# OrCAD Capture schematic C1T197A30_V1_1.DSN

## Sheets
1 01_Block digram: title: Telink-Semi; rev: V1.1; note: C1T197A30
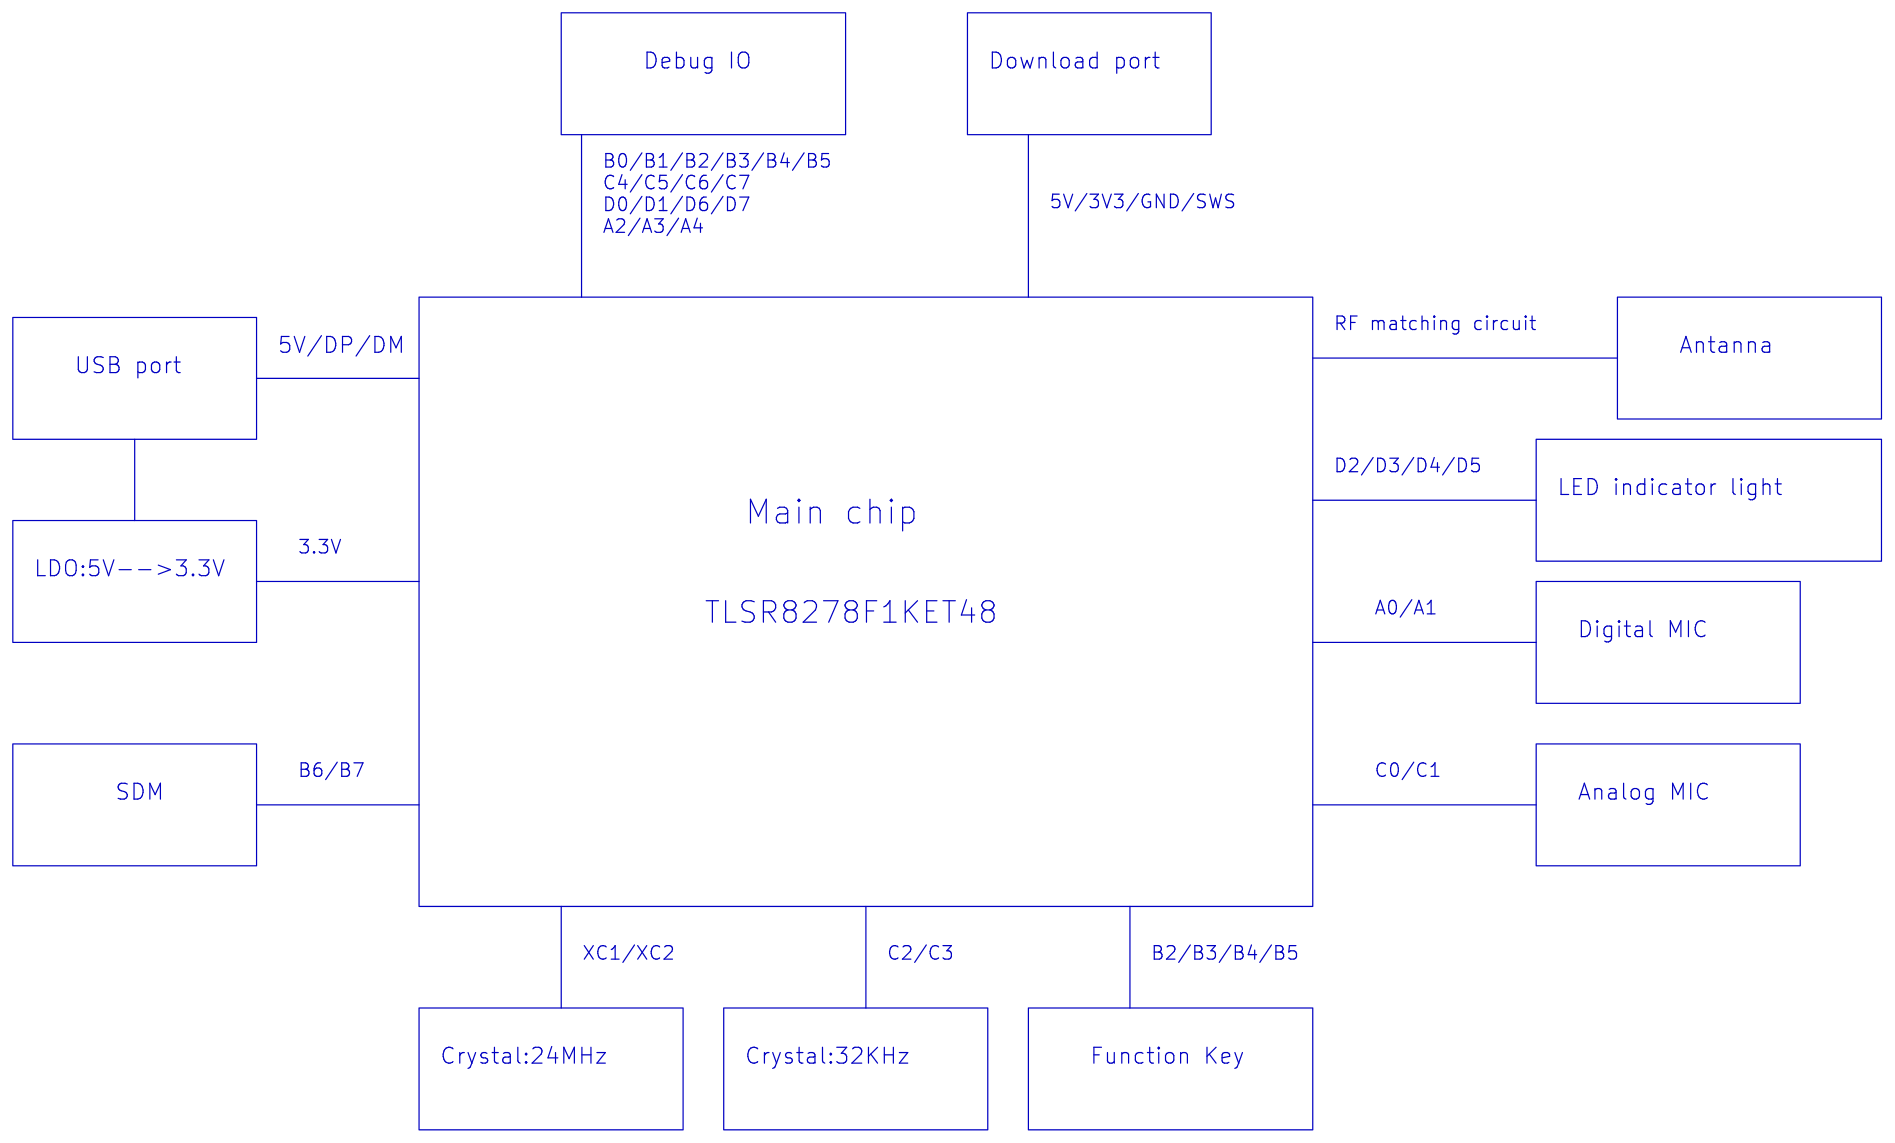
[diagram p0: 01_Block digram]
2 00_Log
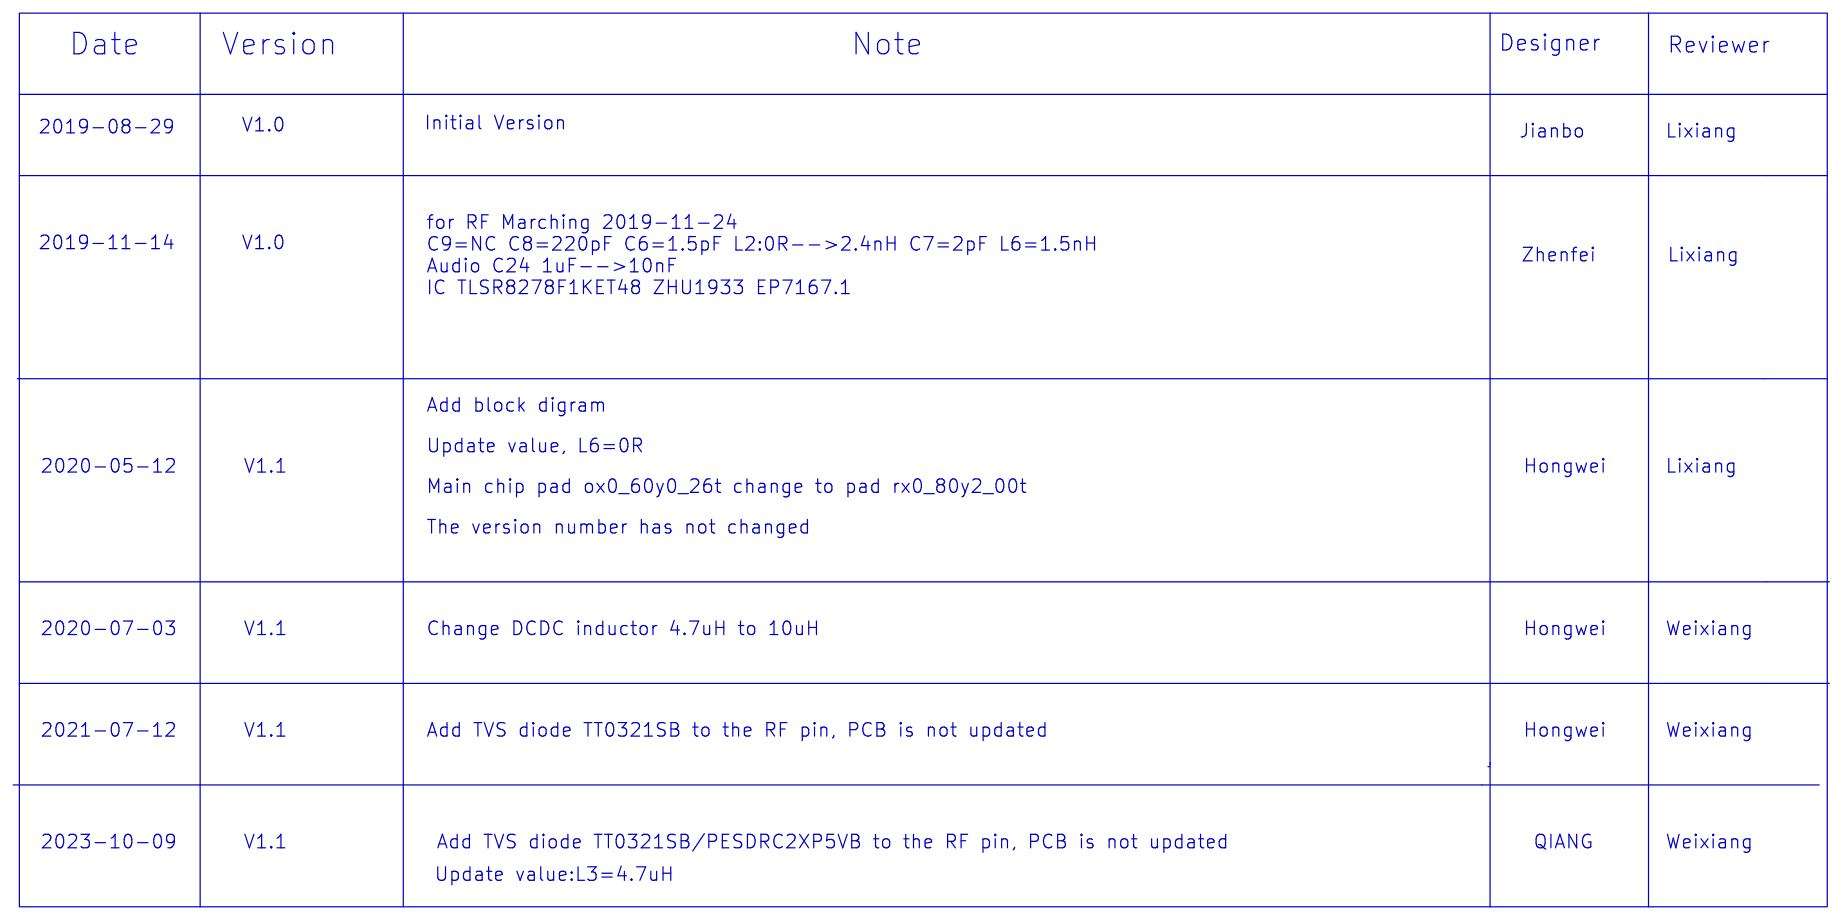
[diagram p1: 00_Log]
3 02_main: size A4
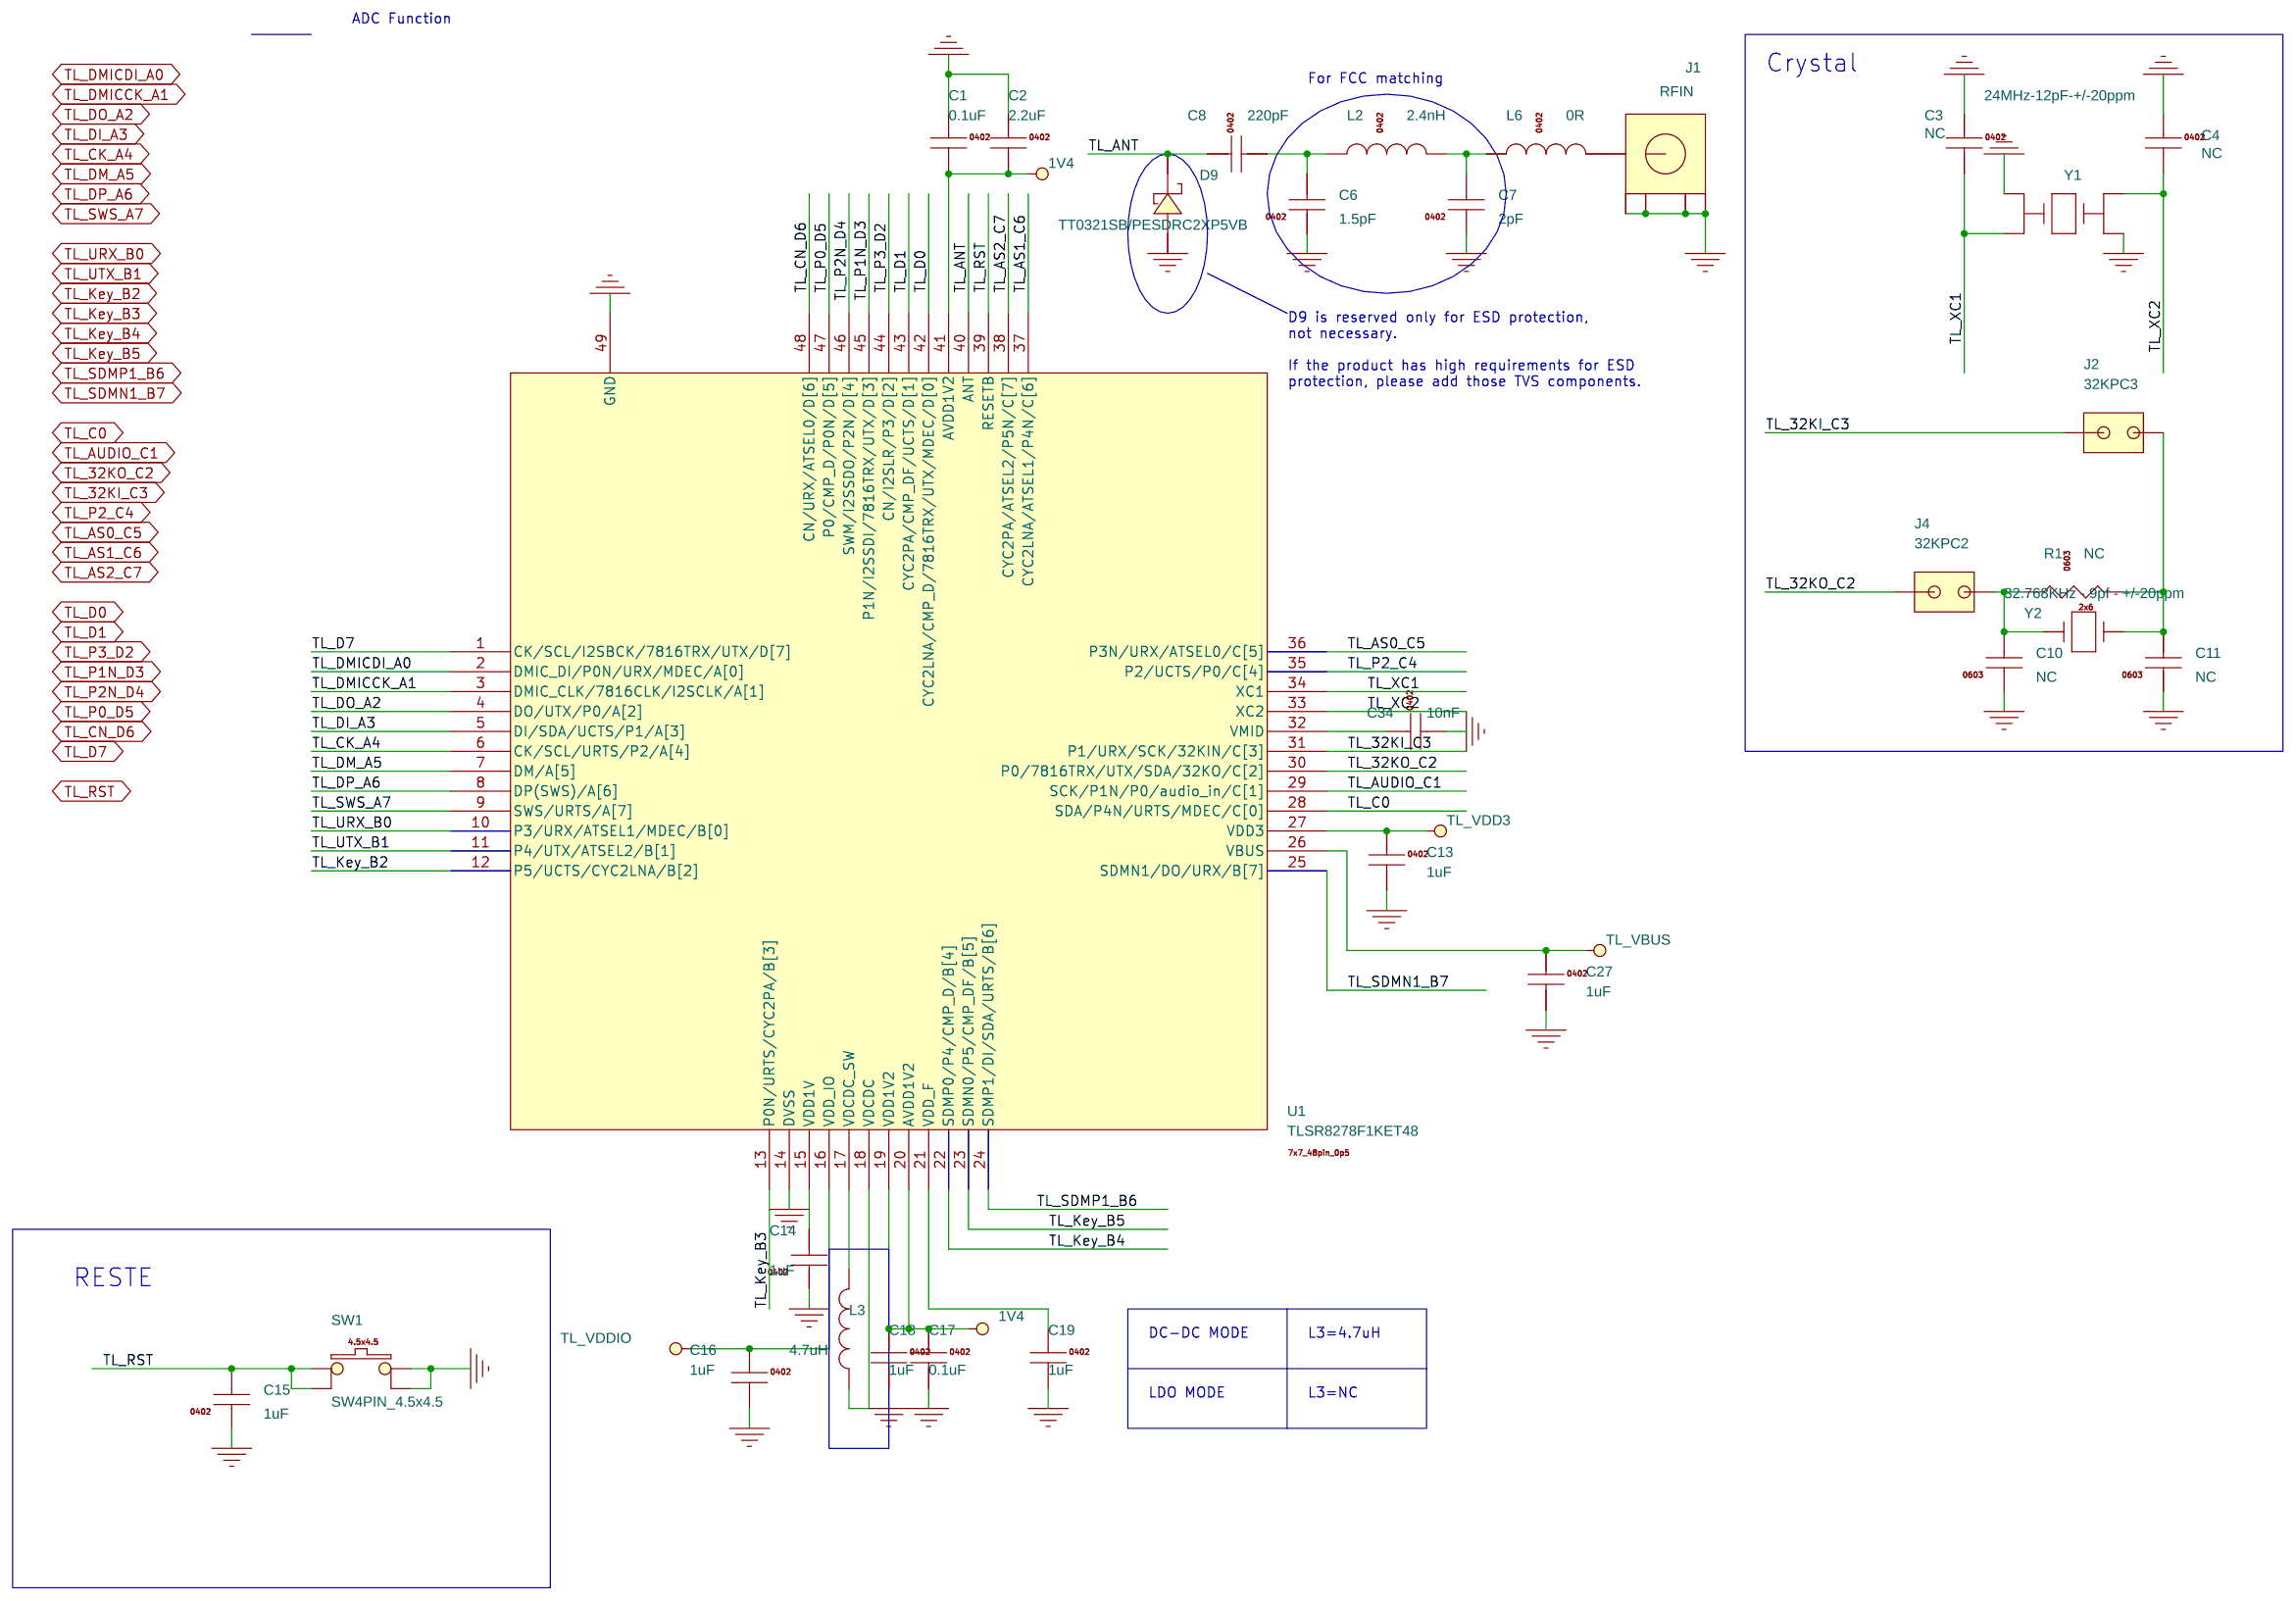
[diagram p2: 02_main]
4 03_Header: size A4
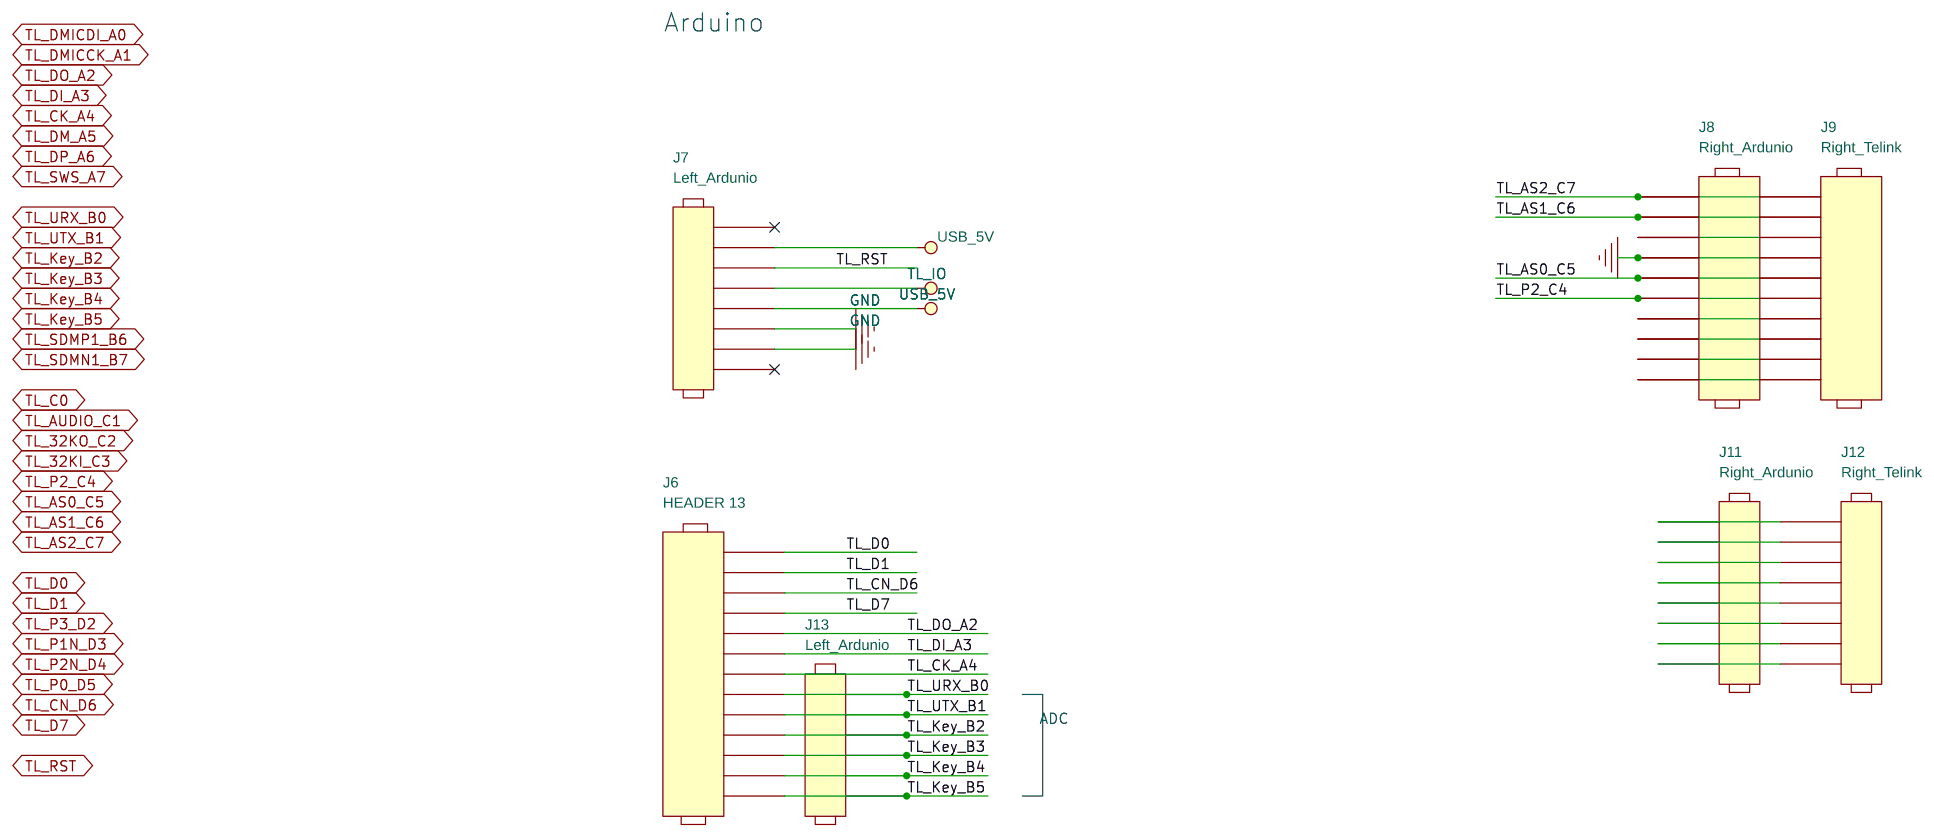
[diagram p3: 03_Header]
5 04_others: size A4
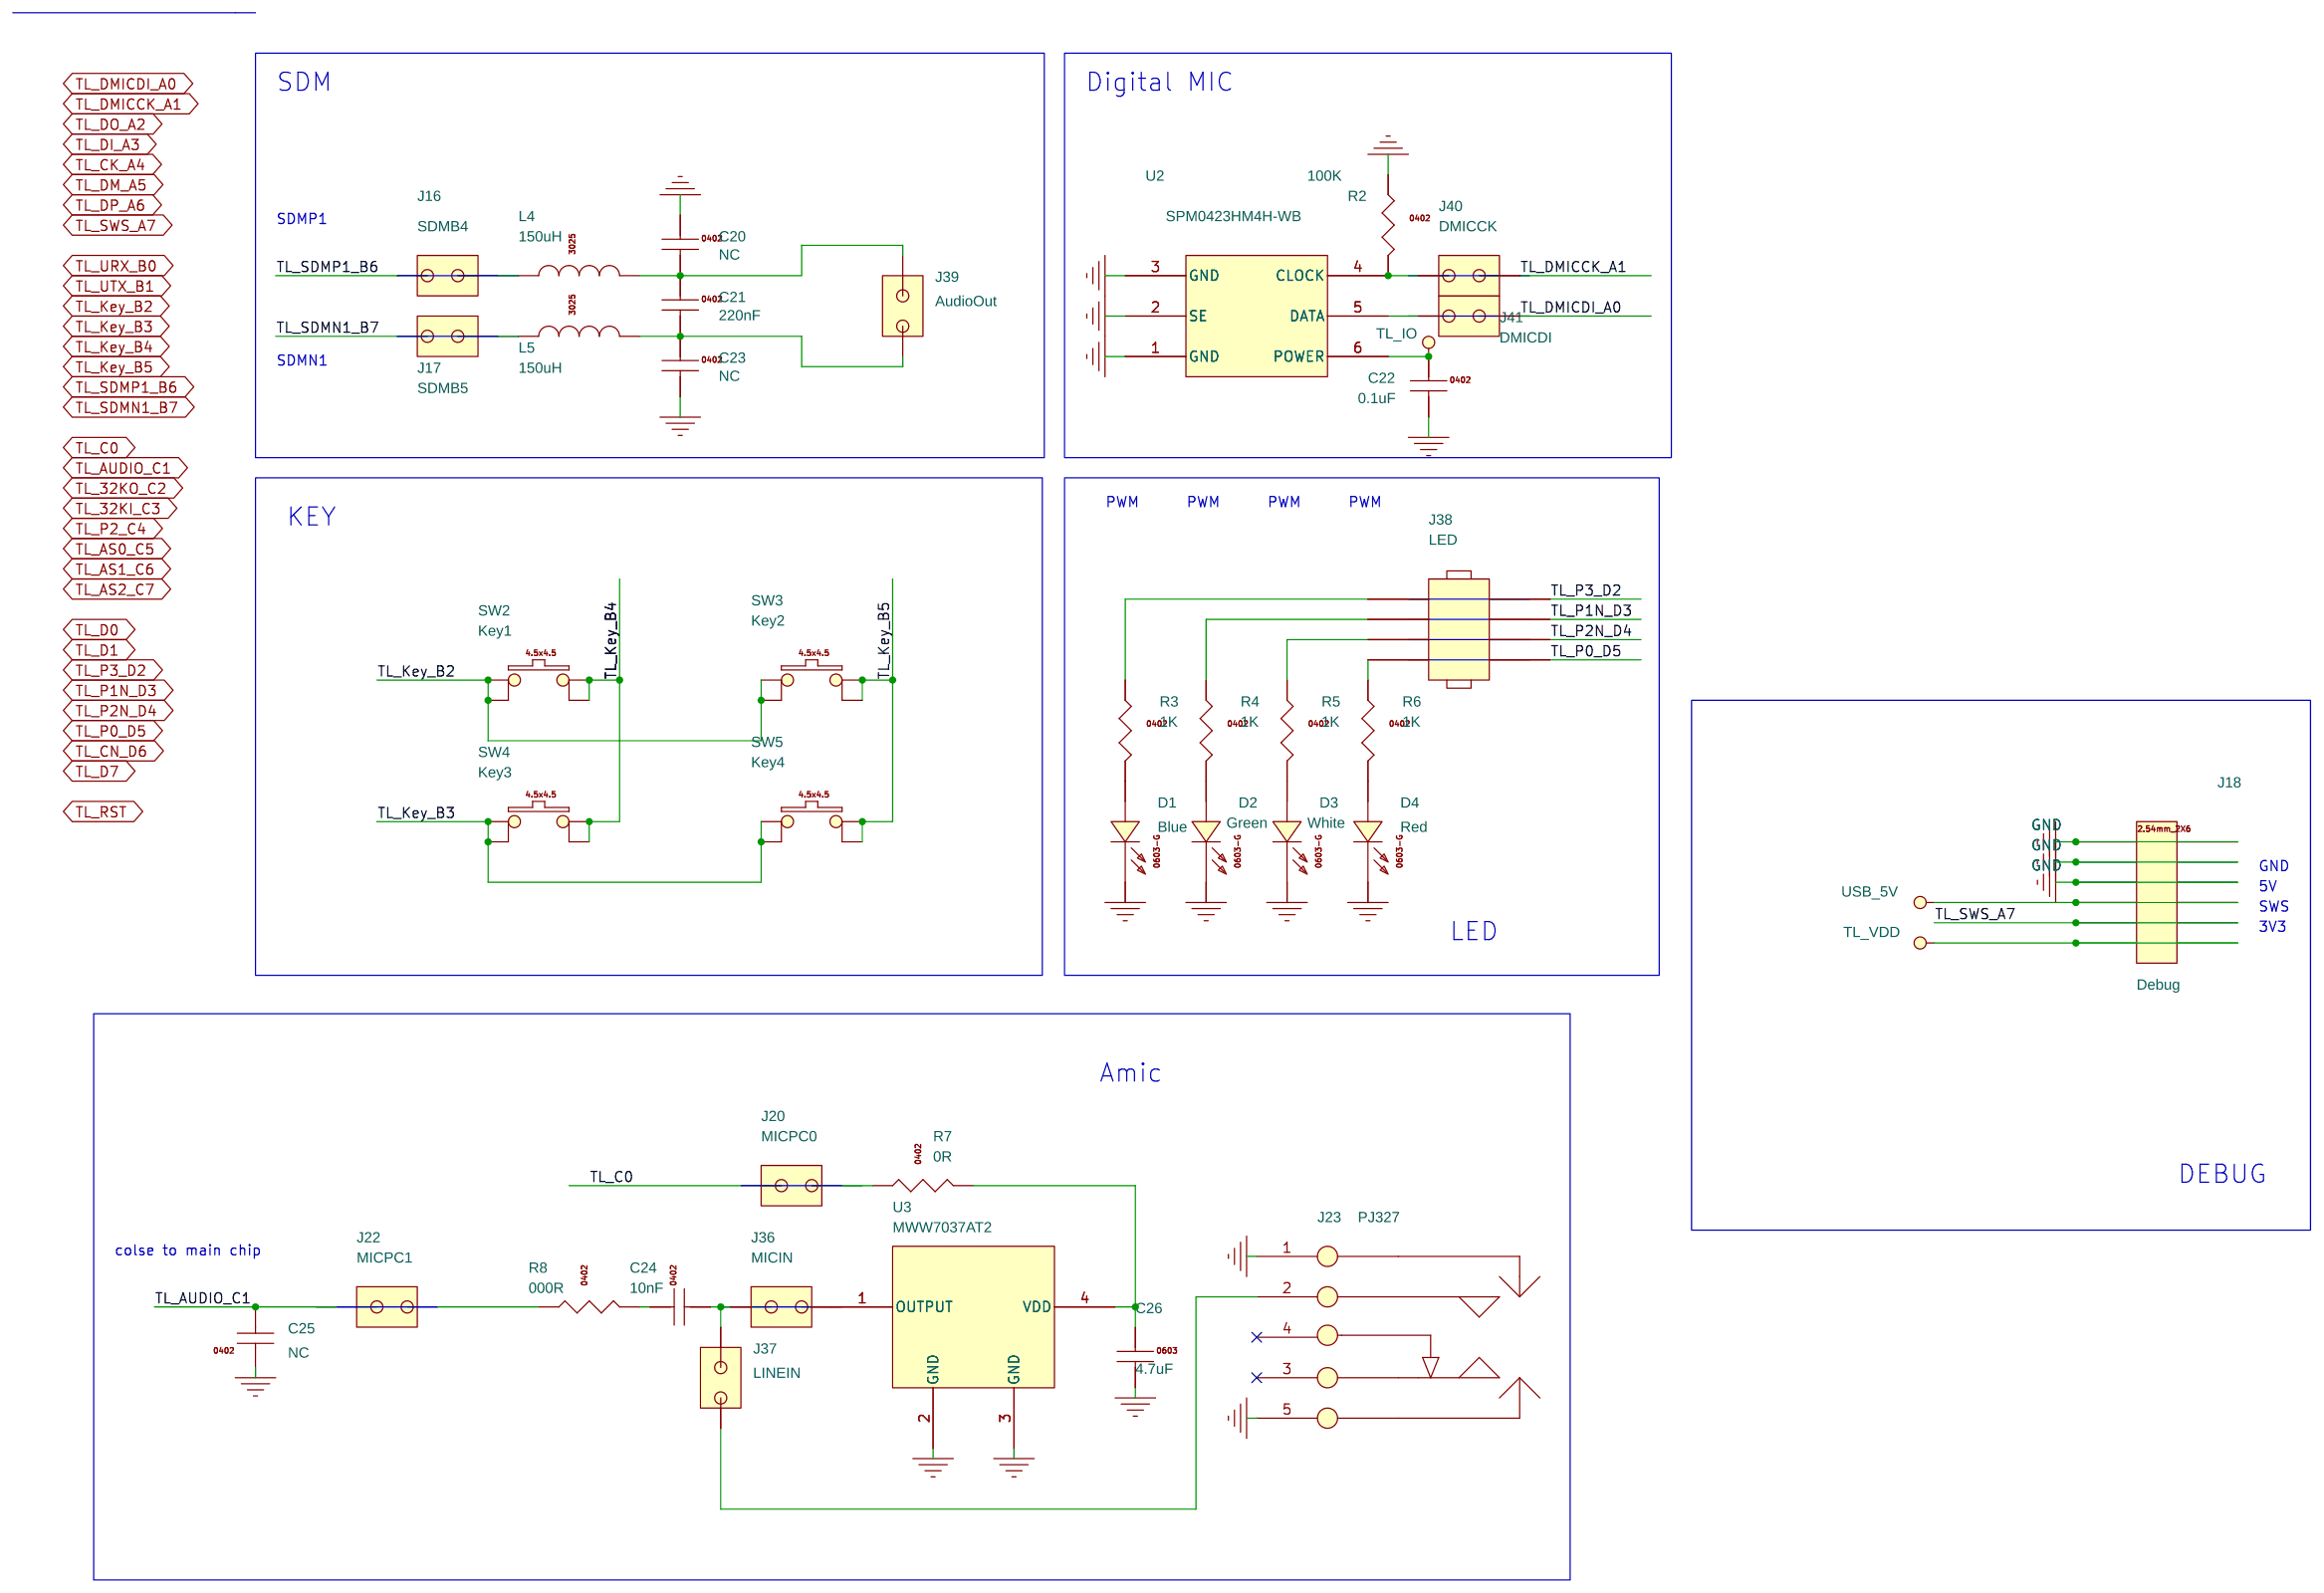
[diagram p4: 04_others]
6 05_power: size A4
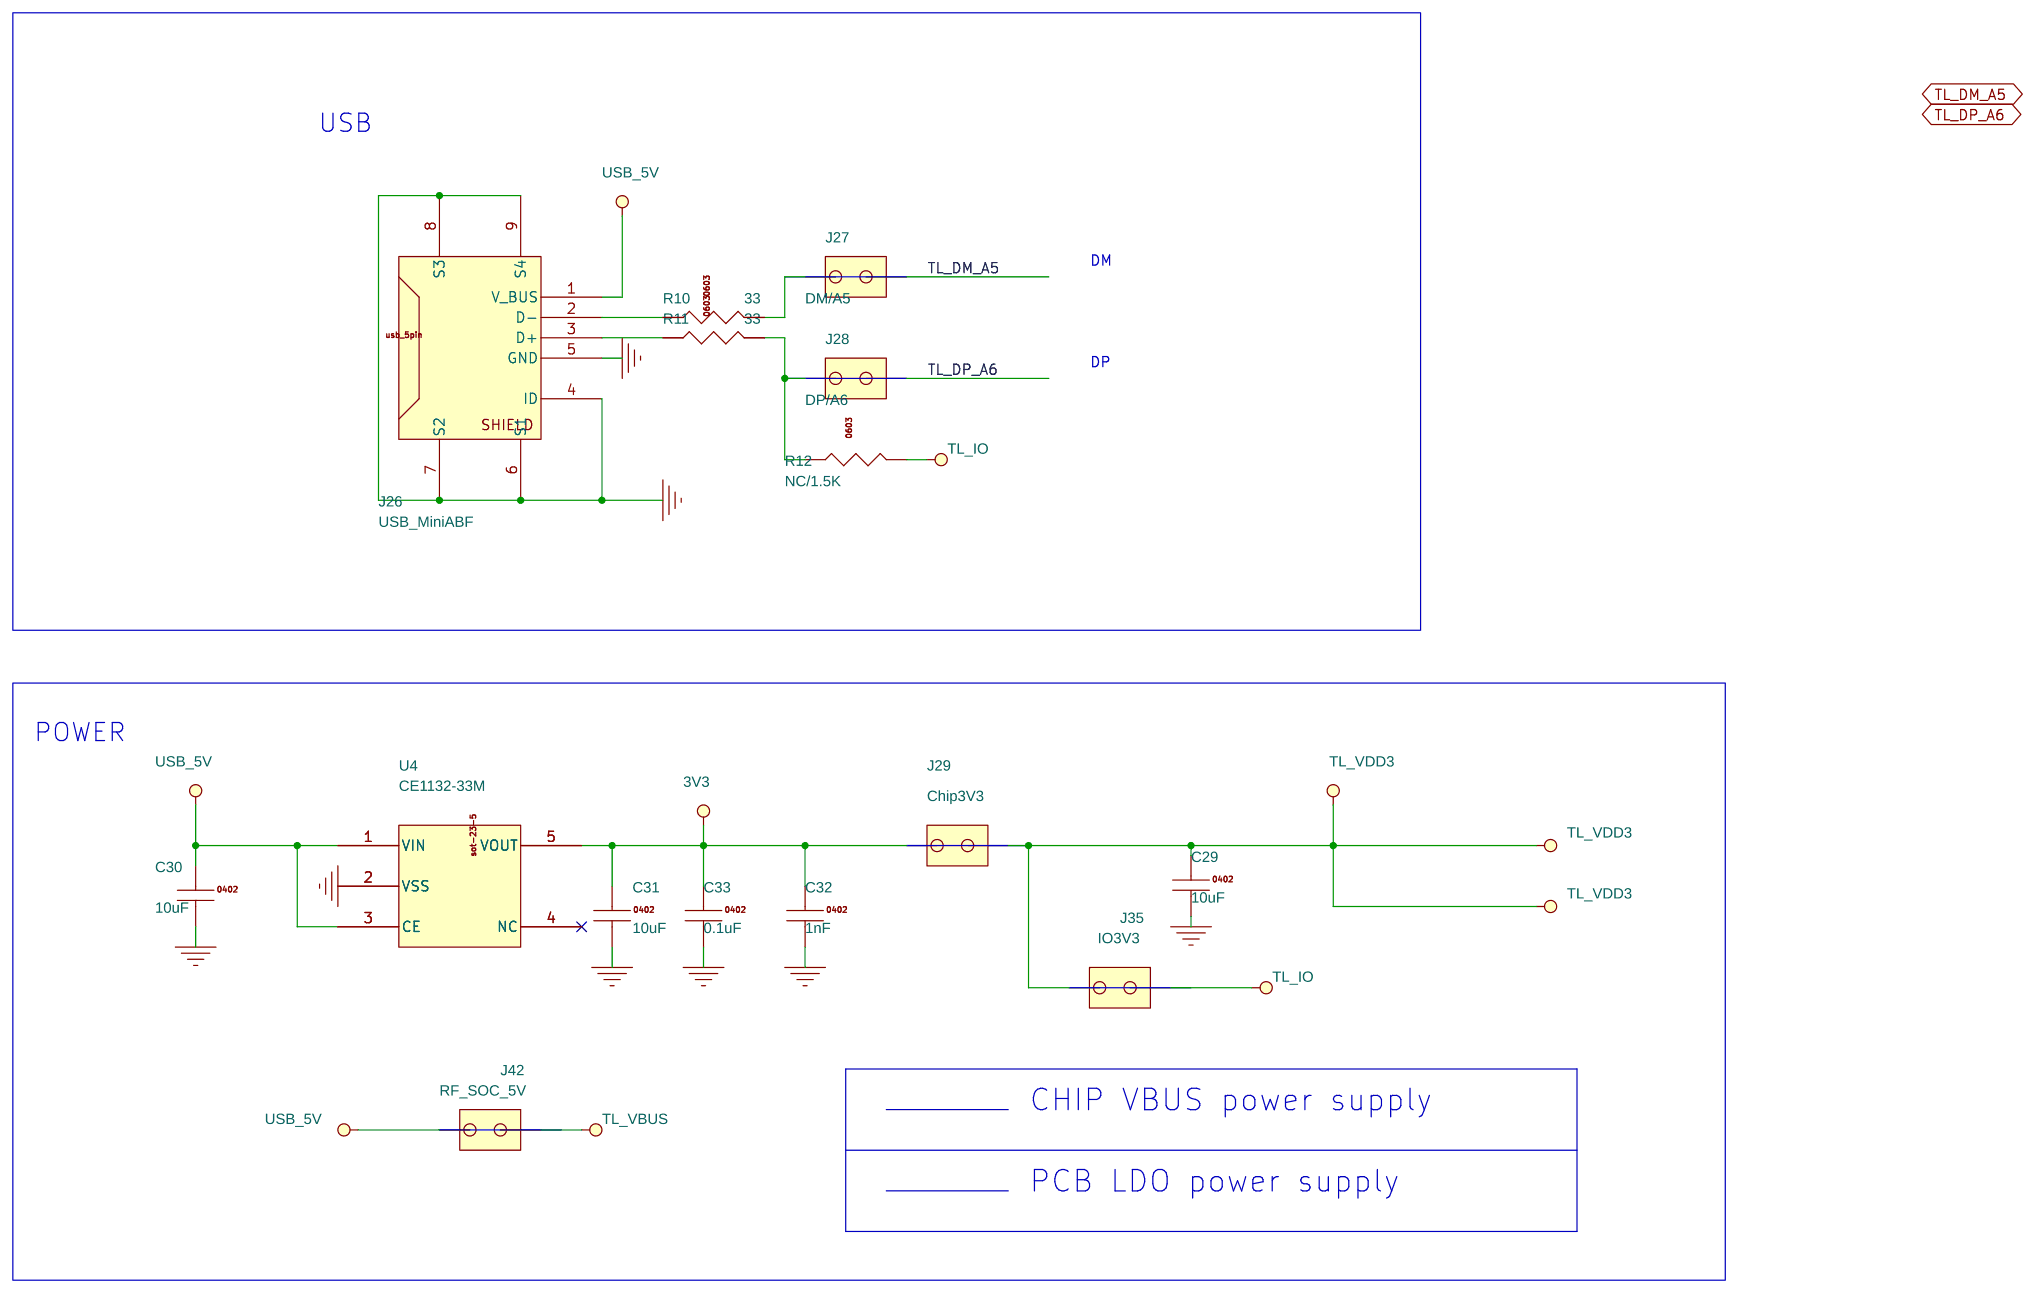
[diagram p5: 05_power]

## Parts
sheet 02_main
C1  0.1uF  [0402]
C2  2.2uF  [0402]
C3  NC  [0402]
C4  NC  [0402]
C6  1.5pF  [0402]
C7  2pF  [0402]
C8  220pF  [0402]
C10  NC  [0402]
C11  NC  [0402]
C13  1uF  [0402]
C14  1uF  [0402]
C15  1uF  [0402]
C16  1uF  [0402]
C17  0.1uF  [0402]
C18  1uF  [0402]
C19  1uF  [0402]
C27  1uF  [0402]
C34  10nF  [0402]
D9  TT0321SB/PESDRC2XP5VB  [SOD-123]
J1  RFIN  [SMA-H]
J2  32KPC3  [HDR254F-1X2X850]
J4  32KPC2  [HDR254F-1X2X850]
L2  2.4nH  [0402]
L3  4.7uH  [2x2_5mm]
L6  0R  [0402]
R1  NC  [0402]
SW1  SW4PIN_4.5x4.5  [BUTDIP4P_5P0X3P0]
U1  TLSR8278F1KET48  [qfn_7x7_48pin_0p5_4p20x4p20_tem]
Y1  24MHz-12pF-+/-20ppm  [OSCCC250X320X110]
Y2  32.768KHz - 9pf - +/-20ppm  [OSC_2x6]
sheet 03_Header
J6  HEADER 13  [hdr254f-1x13x850]
J7  Left_Ardunio  [hdr254f-1x8x850]
J8  Right_Ardunio  [hdr254f-1x10x850]
J9  Right_Telink  [hdr254f-1x10x850]
J11  Right_Ardunio  [hdr254f-1x8x850]
J12  Right_Telink  [hdr254f-1x8x850]
J13  Left_Ardunio  [HDR254F-1X6X850]
sheet 04_others
C20  NC  [0402]
C21  220nF  [0402]
C22  0.1uF  [0402]
C23  NC  [0402]
C24  10nF  [0402]
C25  NC  [0402]
C26  4.7uF  [0603C]
D1  Blue  [0603-LED]
D2  Green  [0603-LED]
D3  White  [0603-LED]
D4  Red  [0603-LED]
J16  SDMB4  [HDR254F-1X2X850]
J17  SDMB5  [HDR254F-1X2X850]
J18  Debug  [hdr254f-1x6x850_telinkdebug]
J20  MICPC0  [HDR254F-1X2X850]
J22  MICPC1  [HDR254F-1X2X850]
J23  PJ327  [PJ-327]
J36  MICIN  [HDR254F-1X2X850]
J37  LINEIN  [HDR254F-1X2X850]
J38  LED  [hdr254f-2x4x850]
J39  AudioOut  [HDR254F-1X2X850]
J40  DMICCK  [HDR254F-1X2X850]
J41  DMICDI  [HDR254F-1X2X850]
L4  150uH  [indm3025x25]
L5  150uH  [indm3025x25]
R2  100K  [0402]
R3  1K  [0402]
R4  1K  [0402]
R5  1K  [0402]
R6  1K  [0402]
R7  0R  [0402]
R8  000R  [0402]
SW2  Key1  [BUTDIP4P_5P0X3P0]
SW3  Key2  [BUTDIP4P_5P0X3P0]
SW4  Key3  [BUTDIP4P_5P0X3P0]
SW5  Key4  [BUTDIP4P_5P0X3P0]
U2  SPM0423HM4H-WB  [DMIC_SPM0423HM4H-WB]
U3  MWW7037AT2  [ga_bfa423_a83]
sheet 05_power
C29  10uF  [0603C]
C30  10uF  [0603c]
C31  10uF  [0603c]
C32  1nF  [0402]
C33  0.1uF  [0402]
J26  USB_MiniABF  [USB-MINI-F5]
J27  DM/A5  [HDR254F-1X2X850]
J28  DP/A6  [HDR254F-1X2X850]
J29  Chip3V3  [HDR254F-1X2X850]
J35  IO3V3  [HDR254F-1X2X850]
J42  RF_SOC_5V  [HDR254F-1X2X850]
R10  33  [0402R]
R11  33  [0402R]
R12  NC/1.5K  [0402R]
U4  CE1132-33M  [sot-23-5]

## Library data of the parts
C1 C2 C13 C16-C19 C22 C27 C29-C34 = C1005X5R1C104K
C3 C4 C20 C23 = C1005_NC
C6-C8 = C1608_NC_0
C10 C11 = C1608_NC
C14 C15 C24 = C1005X5R1C105K
D9 = DIODE_SCHOTTKY_0
J1 = SMA_JACK_2: PART: RF
J2 J4 J16 J17 J20 J22 J27-J29 J35-J37 J39-J42 = B2S_3: PAGE: POWER
L2 L6 = MLK1608_0
L3 = IND_0
R1 = RS0603K102JT
SW1-SW5 = SW4PIN_0.5
U1 = TLSR8278F1KET48_2
Y1 = CRYSTAL4_SM_0
Y2 = OSC_2x6_2pin_16Mhz
J6 = HEADER_13
J7 J11 J12 = HEADER_8
J8 J9 = HEADER_10
J13 = HEADER_6
C21 = C1005X5R1C224M
C25 = C1005C0G1H223J
C26 = C1608X5R0J475M
D1-D4 = 0603D_Green
J18 = CON_0.54mm_2x6
J23 = PJ327_2
J38 = HEADER_4X2
L4 L5 = IND_150uH_3025
R2 = RS0402K104JT
R3-R6 = RS0402K102JT
R7 R8 = RS0402K472JT
U2 = LD1117_SO_0
U3 = MULPS4CX-RM5_0
J26 = USB_MiniABF_5pin
R10 R11 = RS0603K330JT
R12 = RS0603K152JT
U4 = XC6219_6.3V_SOT-23-5

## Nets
1V4: C1.2 C2.2 C17.1 C18.1 U1.19(VDD1V2) U1.20(AVDD1V2) U1.41(AVDD1V2)
3V3: C31.1 C32.1 C33.1 J29.1 U4.5(VOUT)
GND: C1.1 C2.1 C3.1 C4.1 C6.1 C7.1 C10.1 C11.1 C13.2 C14.1 C15.1 C16.2 C17.2 C18.2 C19.2 C20.1 C22.2 C23.2 C25.1 C26.2 C27.2 C29.2 C30.2 C31.2 C32.2 C33.2 C34.2 D1.C(CATHODE) D2.C(CATHODE) D3.C(CATHODE) D4.C(CATHODE) D9.A(ANODE) J1.2 J1.3 J1.4 J1.5 J7.6 J7.7 J8.7 J9.7 J18.1 J18.2 J18.3 J18.10 J18.11 J18.12 J23.1 J23.5 J26.4(ID) J26.5(GND) J26.6(S1) J26.7(S2) J26.8(S3) J26.9(S4) R2.1 SW1.2 SW1.4 U1.14(DVSS) U1.49(GND) U2.1(GND) U2.2(SE) U2.3(GND) U3.2(GND) U3.3(GND) U4.2(VSS) Y1.2 Y1.4
TL_32KI_C3: J2.2 U1.31(P1/URX/SCK/32KIN/C[3])
TL_32KO_C2: J4.2 U1.30(P0/7816TRX/UTX/SDA/32KO/C[2])
TL_ANT: C8.1 D9.C(CATHODE) U1.40(ANT)
TL_AS0_C5: U1.36(P3N/URX/ATSEL0/C[5])
TL_AS0_C5 (page 03_Header): J8.6 J9.6
TL_AS1_C6: U1.37(CYC2LNA/ATSEL1/P4N/C[6])
TL_AS1_C6 (page 03_Header): J8.9 J9.9
TL_AS2_C7: U1.38(CYC2PA/ATSEL2/P5N/C[7])
TL_AS2_C7 (page 03_Header): J8.10 J9.10
TL_AUDIO_C1: U1.29(SCK/P1N/P0/audio_in/C[1])
TL_AUDIO_C1 (page 04_others): C25.2 J22.2
TL_C0: U1.28(SDA/P4N/URTS/MDEC/C[0])
TL_C0 (page 04_others): J20.2
TL_CK_A4: U1.6(CK/SCL/URTS/P2/A[4])
TL_CK_A4 (page 03_Header): J6.7
TL_CN_D6: U1.48(CN/URX/ATSEL0/D[6])
TL_CN_D6 (page 03_Header): J6.11
TL_D0: U1.42(CYC2LNA/CMP_D/7816TRX/UTX/MDEC/D[0])
TL_D0 (page 03_Header): J6.13
TL_D1: U1.43(CYC2PA/CMP_DF/UCTS/D[1])
TL_D1 (page 03_Header): J6.12
TL_D7: U1.1(CK/SCL/I2SBCK/7816TRX/UTX/D[7])
TL_D7 (page 03_Header): J6.10
TL_DI_A3: U1.5(DI/SDA/UCTS/P1/A[3])
TL_DI_A3 (page 03_Header): J6.8
TL_DM_A5: U1.7(DM/A[5])
TL_DM_A5 (page 05_power): J27.2
TL_DMICCK_A1: U1.3(DMIC_CLK/7816CLK/I2SCLK/A[1])
TL_DMICCK_A1 (page 04_others): J40.2
TL_DMICDI_A0: U1.2(DMIC_DI/P0N/URX/MDEC/A[0])
TL_DMICDI_A0 (page 04_others): J41.2
TL_DO_A2: U1.4(DO/UTX/P0/A[2])
TL_DO_A2 (page 03_Header): J6.9
TL_DP_A6: U1.8(DP(SWS)/A[6])
TL_DP_A6 (page 05_power): J28.2
TL_IO: C22.1 J7.4 J35.2 R12.2 U2.6(POWER)
TL_Key_B2: U1.12(P5/UCTS/CYC2LNA/B[2])
TL_Key_B2 (page 03_Header): J6.4 J13.4
TL_Key_B2 (page 04_others): SW2.1 SW2.3 SW3.1 SW3.3
TL_Key_B3: U1.13(P0N/URTS/CYC2PA/B[3])
TL_Key_B3 (page 03_Header): J6.3 J13.3
TL_Key_B3 (page 04_others): SW4.1 SW4.3 SW5.1 SW5.3
TL_Key_B4: U1.22(SDMP0/P4/CMP_D/B[4])
TL_Key_B4 (page 03_Header): J6.2 J13.2
TL_Key_B4 (page 04_others): SW2.2 SW2.4 SW4.2 SW4.4
TL_Key_B5: U1.23(SDMN0/P5/CMP_DF/B[5])
TL_Key_B5 (page 03_Header): J6.1 J13.1
TL_Key_B5 (page 04_others): SW3.2 SW3.4 SW5.2 SW5.4
TL_P0_D5: U1.47(P0/CMP_D/P0N/D[5])
TL_P0_D5 (page 04_others): J38.7
TL_P1N_D3: U1.45(P1N/I2SSDI/7816TRX/UTX/D[3])
TL_P1N_D3 (page 04_others): J38.3
TL_P2_C4: U1.35(P2/UCTS/P0/C[4])
TL_P2_C4 (page 03_Header): J8.5 J9.5
TL_P2N_D4: U1.46(SWM/I2SSDO/P2N/D[4])
TL_P2N_D4 (page 04_others): J38.5
TL_P3_D2: U1.44(CN/I2SLR/P3/D[2])
TL_P3_D2 (page 04_others): J38.1
TL_RST: C15.2 SW1.1 SW1.3 U1.39(RESETB)
TL_RST (page 03_Header): J7.3
TL_SDMN1_B7: U1.25(SDMN1/DO/URX/B[7])
TL_SDMN1_B7 (page 04_others): J17.1
TL_SDMP1_B6: U1.24(SDMP1/DI/SDA/URTS/B[6])
TL_SDMP1_B6 (page 04_others): J16.1
TL_SWS_A7: U1.9(SWS/URTS/A[7])
TL_SWS_A7 (page 04_others): J18.5 J18.8
TL_URX_B0: U1.10(P3/URX/ATSEL1/MDEC/B[0])
TL_URX_B0 (page 03_Header): J6.6 J13.6
TL_UTX_B1: U1.11(P4/UTX/ATSEL2/B[1])
TL_UTX_B1 (page 03_Header): J6.5 J13.5
TL_VBUS: C27.1 J42.2 U1.26(VBUS)
TL_VDD: C13.1 C16.1 C29.1 J18.6 J18.7 J29.2 J35.1 U1.16(VDD_IO) U1.27(VDD3)
TL_XC1: C3.2 U1.34(XC1) Y1.3
TL_XC2: C4.2 U1.33(XC2) Y1.1
USB_5V: C30.1 J7.2 J7.5 J18.4 J18.9 J26.1(V_BUS) J42.1 U4.1(VIN) U4.3(CE)
N19472288: J38.4 R4.1
N19472291: J38.8 R6.1
N19472372: J16.2 L4.1
N19472375: J17.2 L5.1
N19472414: C20.2 C21.1 J39.2 L4.2
N19472431: C21.2 C23.1 J39.1 L5.2
N19472505: J38.2 R3.1
N19497696: J38.6 R5.1
N19519268: C11.2 J2.1 R1.2 Y2.2
N19519271: C10.2 J4.1 R1.1 Y2.1
N19526123: J28.1 R11.2 R12.1
N19526133: J26.3(D+) R11.1
N19526168: J26.2(D-) R10.1
N19527038: J27.1 R10.2
N19581488: J20.1 R7.1
N19581502: C26.1 R7.2 U3.4(VDD)
N19581635: C24.1 R8.2
N19581732: J23.2 J37.1
N19602515: C24.2 J36.2 J37.2
N19603583: J22.1 R8.1
N19606656: J40.1 R2.2 U2.4(CLOCK)
N19606659: J41.1 U2.5(DATA)
N19611817: J8.4 J9.4
N19611824: J8.3 J9.3
N19611831: J8.2 J9.2
N19611838: J8.1 J9.1
N19611845: J8.8 J9.8
N19611852: J11.8 J12.8
N19611859: J11.6 J12.6
N19611866: J11.7 J12.7
N19611873: J11.5 J12.5
N19611880: J11.4 J12.4
N19611887: J11.3 J12.3
N19611894: J11.2 J12.2
N19611901: J11.1 J12.1
N19648539: C34.1 U1.32(VMID)
N19648573: C14.2 U1.15(VDD1V)
N19648583: L3.1 U1.18(VDCDC)
N19648603: L3.2 U1.17(VDCDC_SW)
N19648651: C19.1 U1.21(VDD_F)
N19650305: C6.2 C8.2 L2.1
N19656117: C7.2 L2.2 L6.1
N19671226: D2.A(ANODE) R4.2
N19671229: J36.1 U3.1(OUTPUT)
N19671232: D4.A(ANODE) R6.2
N19671242: D3.A(ANODE) R5.2
N19671246: D1.A(ANODE) R3.2
N19672272: J1.1 L6.2

Not connected (* = marked no-connect by the designer): J7 1* 8*; J23 3* 4*; U4 4(NC)*

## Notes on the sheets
sheet 1
- Debug IO
- Download port
- B0/B1/B2/B3/B4/B5
  C4/C5/C6/C7
  D0/D1/D6/D7
  A2/A3/A4
- 5V/3V3/GND/SWS
- RF matching circuit
- USB port
- 5V/DP/DM
- Antanna
- D2/D3/D4/D5
- Main chip
- LED indicator light
- 3.3V
- LDO:5V-->3.3V
- TLSR8278F1KET48
- A0/A1
- Digital MIC
- B6/B7
- C0/C1
- SDM
- Analog MIC
- XC1/XC2
- C2/C3
- B2/B3/B4/B5
- Crystal:24MHz
- Crystal:32KHz
- Function Key
sheet 2
- Date
- Version
- Note
- Designer
- Reviewer
- 2019-08-29
- V1.0
- Initial Version
- Jianbo
- Lixiang
- for RF Marching 2019-11-24
  C9=NC C8=220pF C6=1.5pF L2:0R-->2.4nH C7=2pF L6=1.5nH
  Audio C24 1uF-->10nF
  IC TLSR8278F1KET48 ZHU1933 EP7167.1
- 2019-11-14
- V1.0
- Zhenfei
- Lixiang
- Add block digram
- Update value, L6=0R
- 2020-05-12
- V1.1
- Main chip pad ox0_60y0_26t change to pad rx0_80y2_00t
- Hongwei
- Lixiang
- The version number has not changed
- 2020-07-03
- V1.1
- Change DCDC inductor 4.7uH to 10uH
- Hongwei
- Weixiang
- 2021-07-12
- V1.1
- Add TVS diode TT0321SB to the RF pin, PCB is not updated
- Hongwei
- Weixiang
- 2023-10-09
- V1.1
- Add TVS diode TT0321SB/PESDRC2XP5VB to the RF pin, PCB is not updated
- QIANG
- Weixiang
- Update value:L3=4.7uH
sheet 3
- ADC Function
- Crystal
- For FCC matching
- D9 is reserved only for ESD protection,
  not necessary.
  If the product has high requirements for ESD
  protection, please add those TVS components.
- RESTE
- DC-DC MODE
- L3=4.7uH
- LDO MODE
- L3=NC
sheet 4
- Arduino
- ADC
sheet 5
- SDM
- Digital MIC
- SDMP1
- SDMN1
- PWM
- PWM
- PWM
- PWM
- KEY
- 5V
- GND
- SWS
- LED
- 3V3
- Amic
- DEBUG
- colse to main chip
sheet 6
- USB
- DM
- DP
- POWER
- CHIP VBUS power supply
- PCB LDO power supply
